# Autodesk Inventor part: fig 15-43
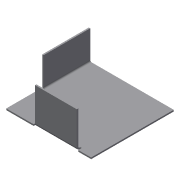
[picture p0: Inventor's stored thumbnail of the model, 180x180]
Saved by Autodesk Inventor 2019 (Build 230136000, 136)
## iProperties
Created: 2005-03
Part Number: fig 15-43
Document SubType Name: Sheet Metal
Designer: CADCIM
Manufacturer: Standard
Standards Organization: Custom
Density: 1 g/cm^3
Sheet Metal Rule: Default
Material: Generic
Appearance: Default
Author: CADCIM
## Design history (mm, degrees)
node "Face1"
  sketch "Sketch1"
    geometry: L1 (-29, -26)-(30, -26); L2 (30, -26)-(30, 31.375); L3 (30, 31.375)-(-29, 31.375); L4 (-29, 31.375)-(-29, -26)
    constraints: 8 end point, 2 parallel, 1 horizontal, 1 perpendicular
node "Flange1"
node "Flange3"
body "Solid1"
face "Plate1" dims "d21" = 1 (= Thickness)
sketch "Sketch2"
  geometry: L1 (25, 0)-(57.375, 0); L2 (57.375, 0)-(57.375, 20); L3 (57.375, 20)-(25, 20); L4 (25, 20)-(25, 0)
  constraints: 8 end point
face "Plate2" dims "d1" = 0, "d2" = 25, "d3" = 1 (= BendReliefWidth), "d5" = 2 (= MinimumRemnant), "d7" = 20, "d8" = 90 deg, "d9" = 1 (= BendRadius), "d21" = 1 (= Thickness)
bend "Bend1" dims "d3" = 1 (= BendReliefWidth), "d4" = 0.5 (= BendReliefDepth), "d5" = 2 (= MinimumRemnant), "d6" = 1 (= BendRadius), "d7" = 20, "d8" = 90 deg, "d9" = 1 (= BendRadius), "d21" = 1 (= Thickness), "SeamGap" = 0.01
sketch "Sketch4"
  geometry: L1 (-39, 0)-(-10, 0); L2 (-10, 0)-(-10, 25); L3 (-10, 25)-(-39, 25); L4 (-39, 25)-(-39, 0)
  constraints: 8 end point
face "Plate4" dims "d21" = 1 (= Thickness), "d22" = 1 (= BendReliefWidth), "d23" = 0.5 (= BendReliefDepth), "d24" = 2 (= MinimumRemnant), "d25" = 1 (= TransitionRadius), "d26" = 20, "d27" = 10, "d28" = 25, "d29" = 90 deg, "d30" = 1 (= BendRadius), "d31" = 4 (= CornerReliefSize), "d32" = 1 (= GapSize), "d33" = 1 (= JacobiRadiusSize), "SeamGap" = 0.01
bend "Bend3" dims "d21" = 1 (= Thickness), "d22" = 1 (= BendReliefWidth), "d23" = 0.5 (= BendReliefDepth), "d24" = 2 (= MinimumRemnant), "d25" = 1 (= TransitionRadius), "d28" = 25, "d29" = 90 deg, "d30" = 1 (= BendRadius), "SeamGap" = 0.01
feature "Corner1" dims "d28" = 25, "d29" = 90 deg, "d31" = 4 (= CornerReliefSize), "d32" = 1 (= GapSize), "d33" = 1 (= JacobiRadiusSize)
other parameters: "Thickness" = 1, "BendRadius" = 1 (= Thickness), "BendReliefWidth" = 1 (= Thickness), "BendReliefDepth" = 0.5 (= 0.5 x Thickness), "CornerReliefSize" = 4 (= 4 x Thickness), "MinimumRemnant" = 2 (= 2 x Thickness), "TransitionRadius" = 1 (= BendRadius), "d0" = 1 (= BendRadius), "JacobiRadiusSize" = 1 (= Thickness), "GapSize" = 1 (= Thickness)
